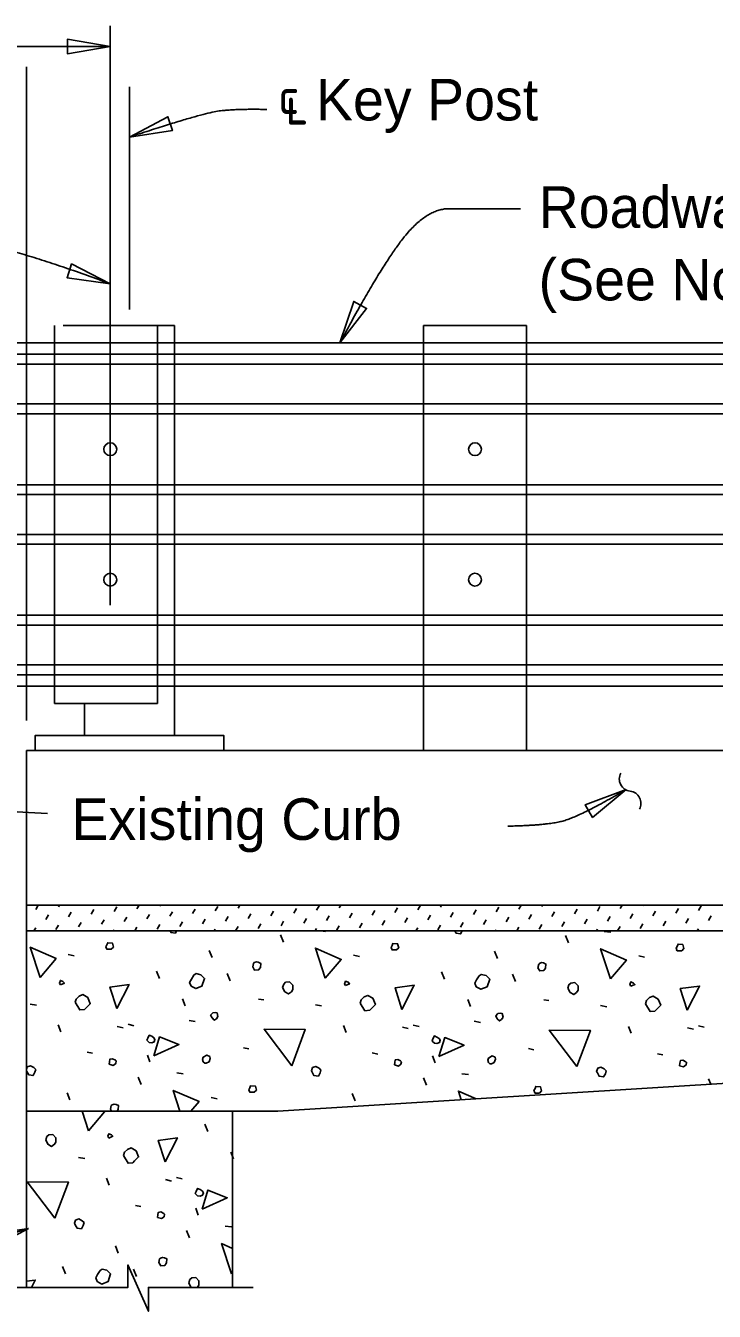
# Model space of a CAD drawing. Extents: x 21526.6 to 21598.7, y 56118.9 to 56155.9.
# Drawn here: x 21554.3 to 21557.64, y 56132.49 to 56138.73 of the extents above; entities that cross this region are included whole.
import ezdxf

# ---------------------------------------------------------------- set-up
doc = ezdxf.new("R2010")
doc.units = 0
for name, color, linetype in [('AdhocPoint_dp', 7, 'Continuous'), ('Border', 7, 'Continuous'), ('Patterning', 7, 'Continuous'), ('PlotBorder_dp', 7, 'Continuous'), ('SheetBorder_dp', 7, 'Continuous')]:
    doc.layers.add(name, color=color, linetype=linetype)

msp = doc.modelspace()

# ---------------------------------------------------------------- linework, layer by layer
at = {"layer": 'AdhocPoint_dp'}
for p, q in [((21554.3017, 56135.21), (21555.3017, 56135.21)), ((21554.3018, 56135.2101), (21554.3018, 56132.6054)), ((21554.3018, 56135.21), (21562.4118, 56135.21)), ((21565.8764, 56134.4601), (21554.3018, 56134.4601)), ((21554.3018, 56134.3351), (21565.8764, 56134.3351)), ((21559.5217, 56133.71), (21555.5217, 56133.46)), ((21555.5217, 56133.46), (21554.3017, 56133.46)), ((21555.3018, 56133.4601), (21555.3018, 56132.6054))]:
    msp.add_line(p, q, dxfattribs=at)
at = {"layer": 'Patterning'}
for p, q in [((21554.7081, 56135.9163), (21554.7081, 56138.7275)), ((21554.8018, 56138.4301), (21554.8018, 56137.3509)), ((21554.4372, 56137.2725), (21554.4372, 56135.4392)), ((21554.479, 56137.2725), (21555.0205, 56137.2725)), ((21554.9372, 56137.2725), (21554.9372, 56135.4392)), ((21556.2288, 56137.2725), (21556.2288, 56135.21)), ((21556.2288, 56137.2725), (21556.7288, 56137.2725)), ((21556.7288, 56137.2725), (21556.7288, 56135.21)), ((21554.3461, 56134.4388), (21554.3585, 56134.4601)), ((21554.4568, 56134.4517), (21554.4616, 56134.4601)), ((21554.8375, 56134.4418), (21554.8481, 56134.4601)), ((21554.9481, 56134.4548), (21554.9512, 56134.4601)), ((21555.3289, 56134.4448), (21555.3377, 56134.4601)), ((21555.4395, 56134.4578), (21555.4409, 56134.4601)), ((21555.7096, 56134.4349), (21555.7226, 56134.4573)), ((21555.8202, 56134.4478), (21555.8273, 56134.4601)), ((21556.201, 56134.4379), (21556.2138, 56134.4601)), ((21556.3116, 56134.4509), (21556.317, 56134.4601)), ((21556.6923, 56134.4409), (21556.7035, 56134.4601)), ((21556.803, 56134.4539), (21556.8066, 56134.4601)), ((21557.1837, 56134.4439), (21557.1931, 56134.4601)), ((21557.2943, 56134.4569), (21557.2962, 56134.4601)), ((21557.5644, 56134.434), (21557.5774, 56134.4564)), ((21554.395, 56134.3899), (21554.4079, 56134.4123)), ((21554.5056, 56134.4029), (21554.5186, 56134.4253)), ((21554.6162, 56134.4159), (21554.6292, 56134.4383)), ((21554.7269, 56134.4288), (21554.7398, 56134.4512)), ((21554.7757, 56134.38), (21554.7887, 56134.4024)), ((21554.8863, 56134.393), (21554.8993, 56134.4154)), ((21554.997, 56134.4059), (21555.0099, 56134.4283)), ((21555.1076, 56134.4189), (21555.1206, 56134.4413)), ((21555.2182, 56134.4319), (21555.2312, 56134.4542)), ((21555.2671, 56134.383), (21555.28, 56134.4054)), ((21555.3777, 56134.396), (21555.3907, 56134.4184)), ((21555.4883, 56134.4089), (21555.5013, 56134.4313)), ((21555.599, 56134.4219), (21555.6119, 56134.4443)), ((21555.6478, 56134.3731), (21555.6608, 56134.3955)), ((21555.7584, 56134.386), (21555.7714, 56134.4084)), ((21555.8691, 56134.399), (21555.882, 56134.4214)), ((21555.9797, 56134.412), (21555.9927, 56134.4344)), ((21556.0903, 56134.4249), (21556.1033, 56134.4473)), ((21556.1392, 56134.3761), (21556.1521, 56134.3985)), ((21556.2498, 56134.3891), (21556.2628, 56134.4115)), ((21556.3604, 56134.402), (21556.3734, 56134.4244)), ((21556.4711, 56134.415), (21556.484, 56134.4374)), ((21556.5817, 56134.428), (21556.5947, 56134.4503)), ((21556.6305, 56134.3791), (21556.6435, 56134.4015)), ((21556.7412, 56134.3921), (21556.7541, 56134.4145)), ((21556.8518, 56134.405), (21556.8648, 56134.4274)), ((21556.9624, 56134.418), (21556.9754, 56134.4404)), ((21557.0731, 56134.431), (21557.086, 56134.4534)), ((21557.1219, 56134.3821), (21557.1349, 56134.4045)), ((21557.2325, 56134.3951), (21557.2455, 56134.4175)), ((21557.3432, 56134.4081), (21557.3561, 56134.4305)), ((21557.4538, 56134.421), (21557.4668, 56134.4434)), ((21557.5026, 56134.3722), (21557.5156, 56134.3946)), ((21557.6133, 56134.3852), (21557.6262, 56134.4075)), ((21554.3372, 56134.3351), (21554.3461, 56134.3505)), ((21554.4438, 56134.3411), (21554.4568, 56134.3635)), ((21554.5544, 56134.3541), (21554.5674, 56134.3765)), ((21554.6651, 56134.367), (21554.678, 56134.3894)), ((21554.7237, 56134.3351), (21554.7269, 56134.3406)), ((21554.8268, 56134.3351), (21554.8375, 56134.3536)), ((21554.9352, 56134.3441), (21554.9481, 56134.3665)), ((21555.0458, 56134.3571), (21555.0588, 56134.3795)), ((21555.1564, 56134.3701), (21555.1694, 56134.3925)), ((21555.2133, 56134.3351), (21555.2182, 56134.3436)), ((21555.3164, 56134.3351), (21555.3289, 56134.3566)), ((21555.4265, 56134.3472), (21555.4395, 56134.3695)), ((21555.5372, 56134.3601), (21555.5501, 56134.3825)), ((21555.7029, 56134.3351), (21555.7096, 56134.3466)), ((21555.7313, 56134.3351), (21555.7532, 56134.3326)), ((21555.8073, 56134.3372), (21555.8202, 56134.3596)), ((21555.9179, 56134.3502), (21555.9309, 56134.3726)), ((21556.0285, 56134.3631), (21556.0415, 56134.3855)), ((21556.0894, 56134.3351), (21556.0903, 56134.3367)), ((21556.1925, 56134.3351), (21556.201, 56134.3497)), ((21556.2986, 56134.3402), (21556.3116, 56134.3626)), ((21556.4093, 56134.3532), (21556.4222, 56134.3756)), ((21556.5199, 56134.3662), (21556.5329, 56134.3885)), ((21556.579, 56134.3351), (21556.5817, 56134.3397)), ((21556.6821, 56134.3351), (21556.6923, 56134.3527)), ((21556.79, 56134.3432), (21556.803, 56134.3656)), ((21556.9006, 56134.3562), (21556.9136, 56134.3786)), ((21557.0113, 56134.3692), (21557.0242, 56134.3916)), ((21557.0686, 56134.3351), (21557.0731, 56134.3427)), ((21557.1061, 56134.3326), (21557.1379, 56134.3291)), ((21557.1718, 56134.3351), (21557.1837, 56134.3557)), ((21557.2814, 56134.3463), (21557.2943, 56134.3687)), ((21557.392, 56134.3592), (21557.405, 56134.3816)), ((21557.5582, 56134.3351), (21557.5644, 56134.3458)), ((21555.5488, 56134.2802), (21555.5346, 56134.3156)), ((21556.9334, 56134.2767), (21556.9193, 56134.312)), ((21554.5046, 56134.2213), (21554.5329, 56134.2142)), ((21555.2029, 56134.2054), (21555.1888, 56134.2407)), ((21555.8893, 56134.2177), (21555.9176, 56134.2107)), ((21556.5876, 56134.2018), (21556.5734, 56134.2372)), ((21557.274, 56134.2142), (21557.3023, 56134.2071)), ((21554.9466, 56134.1046), (21554.9324, 56134.1399)), ((21555.2907, 56134.0928), (21555.2765, 56134.1282)), ((21556.3313, 56134.1011), (21556.3171, 56134.1364)), ((21556.6753, 56134.0893), (21556.6612, 56134.1247)), ((21554.3196, 56133.9797), (21554.3497, 56133.9744)), ((21555.0721, 56133.972), (21555.0597, 56134.0056)), ((21555.4286, 56134.0045), (21555.4533, 56134.0009)), ((21555.7043, 56133.9762), (21555.7344, 56133.9709)), ((21556.4568, 56133.9685), (21556.4444, 56134.0021)), ((21556.8132, 56134.0009), (21556.838, 56133.9974)), ((21557.089, 56133.9726), (21557.1191, 56133.9673)), ((21555.0909, 56133.9002), (21555.121, 56133.8949)), ((21556.4756, 56133.8966), (21556.5056, 56133.8913)), ((21554.4681, 56133.8454), (21554.4558, 56133.8789)), ((21554.7421, 56133.8719), (21554.7704, 56133.8648)), ((21554.7945, 56133.8819), (21554.8228, 56133.8748)), ((21555.8528, 56133.8418), (21555.8404, 56133.8754)), ((21556.1268, 56133.8683), (21556.1551, 56133.8613)), ((21556.1792, 56133.8783), (21556.2075, 56133.8712)), ((21557.2375, 56133.8383), (21557.2251, 56133.8719)), ((21557.5115, 56133.8648), (21557.5398, 56133.8577)), ((21557.5639, 56133.8748), (21557.5922, 56133.8677)), ((21554.5954, 56133.7464), (21554.6219, 56133.7411)), ((21554.9006, 56133.6993), (21554.8882, 56133.7328)), ((21555.3543, 56133.7676), (21555.3808, 56133.7623)), ((21555.9801, 56133.7428), (21556.0066, 56133.7375)), ((21556.2853, 56133.6957), (21556.2729, 56133.7293)), ((21556.739, 56133.764), (21556.7655, 56133.7587)), ((21557.3648, 56133.7393), (21557.3913, 56133.734)), ((21555.0308, 56133.6456), (21555.0626, 56133.6421)), ((21554.8582, 56133.5897), (21554.844, 56133.625)), ((21556.2429, 56133.5861), (21556.2287, 56133.6215)), ((21556.4155, 56133.6421), (21556.4473, 56133.6385)), ((21557.624, 56133.5914), (21557.6134, 56133.6179)), ((21554.5123, 56133.5148), (21554.4982, 56133.5501)), ((21555.1987, 56133.5272), (21555.227, 56133.5201)), ((21555.897, 56133.5112), (21555.8829, 56133.5466)), ((21555.1813, 56133.3611), (21555.1671, 56133.3965)), ((21554.3017, 56133.2612), (21554.3033, 56133.261)), ((21554.5543, 56133.2362), (21554.5844, 56133.2309)), ((21555.3068, 56133.2285), (21555.2944, 56133.2621)), ((21554.7028, 56133.1019), (21554.6905, 56133.1355)), ((21554.9768, 56133.1284), (21555.0051, 56133.1213)), ((21555.0292, 56133.1384), (21555.0575, 56133.1313)), ((21554.8301, 56133.0029), (21554.8566, 56132.9976)), ((21555.1353, 56132.9558), (21555.1229, 56132.9894)), ((21555.2655, 56132.9021), (21555.2973, 56132.8986)), ((21555.0929, 56132.8462), (21555.0787, 56132.8815)), ((21554.747, 56132.7713), (21554.7329, 56132.8067)), ((21554.4907, 56132.6706), (21554.4766, 56132.7059)), ((21554.8348, 56132.6588), (21554.8206, 56132.6942))]:
    msp.add_line(p, q, dxfattribs=at)
for points in [[(21554.9988, 56134.3351), (21555.0031, 56134.3273), (21555.0244, 56134.3238), (21555.0306, 56134.3351)], [(21556.3816, 56134.3351), (21556.3878, 56134.3238), (21556.409, 56134.3203), (21556.4173, 56134.3351)], [(21554.692, 56134.246), (21554.7132, 56134.246), (21554.7238, 56134.2566), (21554.7185, 56134.2761), (21554.6956, 56134.2778), (21554.692, 56134.2672), (21554.6867, 56134.2584), (21554.692, 56134.246), (21554.6885, 56134.2495)], [(21556.0767, 56134.2425), (21556.0979, 56134.2425), (21556.1085, 56134.2531), (21556.1032, 56134.2725), (21556.0802, 56134.2743), (21556.0767, 56134.2637), (21556.0714, 56134.2549), (21556.0767, 56134.2425), (21556.0732, 56134.246)], [(21557.4614, 56134.2389), (21557.4826, 56134.2389), (21557.4932, 56134.2495), (21557.4879, 56134.269), (21557.4649, 56134.2708), (21557.4614, 56134.2602), (21557.4561, 56134.2513), (21557.4614, 56134.2389), (21557.4578, 56134.2425)], [(21554.3674, 56134.1088), (21554.3196, 56134.2555), (21554.4452, 56134.2007), (21554.3674, 56134.1088)], [(21555.7521, 56134.1052), (21555.7043, 56134.2519), (21555.8298, 56134.1971), (21555.7521, 56134.1052)], [(21557.1367, 56134.1017), (21557.089, 56134.2484), (21557.2145, 56134.1936), (21557.1367, 56134.1017)], [(21555.4003, 56134.16), (21555.4091, 56134.1441), (21555.4286, 56134.1459), (21555.4374, 56134.1582), (21555.4392, 56134.1777), (21555.4268, 56134.183), (21555.4179, 56134.1848), (21555.4073, 56134.1812), (21555.4038, 56134.1777), (21555.4003, 56134.16)], [(21556.7849, 56134.1565), (21556.7938, 56134.1406), (21556.8132, 56134.1423), (21556.8221, 56134.1547), (21556.8238, 56134.1742), (21556.8115, 56134.1795), (21556.8026, 56134.1812), (21556.792, 56134.1777), (21556.7885, 56134.1742), (21556.7849, 56134.1565)], [(21554.4664, 56134.0734), (21554.4858, 56134.0822), (21554.4787, 56134.0893), (21554.4664, 56134.0946), (21554.4611, 56134.0822), (21554.4664, 56134.0734)], [(21555.1004, 56134.0675), (21555.1234, 56134.0551), (21555.1534, 56134.0675), (21555.1658, 56134.1046), (21555.1481, 56134.1223), (21555.1251, 56134.1276), (21555.1145, 56134.1205), (21555.1021, 56134.1011), (21555.0933, 56134.0851), (21555.1004, 56134.0675)], [(21555.5452, 56134.061), (21555.5558, 56134.0398), (21555.5735, 56134.0292), (21555.5876, 56134.0398), (21555.5947, 56134.0504), (21555.5947, 56134.0716), (21555.5788, 56134.0875), (21555.5594, 56134.0858), (21555.5505, 56134.0769), (21555.5452, 56134.061)], [(21555.851, 56134.0699), (21555.8705, 56134.0787), (21555.8634, 56134.0858), (21555.851, 56134.0911), (21555.8457, 56134.0787), (21555.851, 56134.0699)], [(21556.485, 56134.0639), (21556.508, 56134.0516), (21556.5381, 56134.0639), (21556.5505, 56134.1011), (21556.5328, 56134.1187), (21556.5098, 56134.124), (21556.4992, 56134.117), (21556.4868, 56134.0975), (21556.478, 56134.0816), (21556.485, 56134.0639)], [(21556.9299, 56134.0575), (21556.9405, 56134.0363), (21556.9582, 56134.0257), (21556.9723, 56134.0363), (21556.9794, 56134.0469), (21556.9794, 56134.0681), (21556.9635, 56134.084), (21556.944, 56134.0822), (21556.9352, 56134.0734), (21556.9299, 56134.0575)], [(21557.2357, 56134.0663), (21557.2552, 56134.0752), (21557.2481, 56134.0822), (21557.2357, 56134.0875), (21557.2304, 56134.0752), (21557.2357, 56134.0663)], [(21554.5371, 56133.9885), (21554.5601, 56133.9514), (21554.583, 56133.9532), (21554.5919, 56133.962), (21554.6113, 56133.9815), (21554.599, 56134.0115), (21554.5742, 56134.0257), (21554.5565, 56134.0186), (21554.5424, 56134.0045), (21554.5371, 56133.9885)], [(21554.7397, 56133.9579), (21554.7062, 56134.0622), (21554.7999, 56134.0745), (21554.7397, 56133.9579)], [(21555.9218, 56133.985), (21555.9447, 56133.9479), (21555.9677, 56133.9497), (21555.9766, 56133.9585), (21555.996, 56133.9779), (21555.9836, 56134.008), (21555.9589, 56134.0221), (21555.9412, 56134.0151), (21555.9271, 56134.0009), (21555.9218, 56133.985)], [(21556.1244, 56133.9543), (21556.0908, 56134.0586), (21556.1845, 56134.071), (21556.1244, 56133.9543)], [(21557.5091, 56133.9508), (21557.4755, 56134.0551), (21557.5692, 56134.0675), (21557.5091, 56133.9508)], [(21557.3064, 56133.9815), (21557.3294, 56133.9444), (21557.3524, 56133.9461), (21557.3612, 56133.955), (21557.3807, 56133.9744), (21557.3683, 56134.0045), (21557.3436, 56134.0186), (21557.3259, 56134.0115), (21557.3117, 56133.9974), (21557.3064, 56133.9815)], [(21555.2023, 56133.9125), (21555.2129, 56133.9019), (21555.2235, 56133.909), (21555.2306, 56133.9196), (21555.227, 56133.9373), (21555.2182, 56133.939), (21555.2058, 56133.9373), (21555.1952, 56133.9267), (21555.2023, 56133.9125)], [(21556.587, 56133.909), (21556.5976, 56133.8984), (21556.6082, 56133.9055), (21556.6152, 56133.9161), (21556.6117, 56133.9337), (21556.6029, 56133.9355), (21556.5905, 56133.9337), (21556.5799, 56133.9231), (21556.587, 56133.909)], [(21555.5894, 56133.681), (21555.4551, 56133.8577), (21555.6548, 56133.856), (21555.5894, 56133.681)], [(21556.9741, 56133.6774), (21556.8397, 56133.8542), (21557.0395, 56133.8524), (21556.9741, 56133.6774)], [(21554.8971, 56133.7935), (21554.9095, 56133.7917), (21554.9218, 56133.797), (21554.9254, 56133.8076), (21554.9201, 56133.8164), (21554.9095, 56133.8235), (21554.8971, 56133.8288), (21554.89, 56133.8147), (21554.8865, 56133.8041), (21554.8971, 56133.7935)], [(21554.9194, 56133.7287), (21554.9477, 56133.8206), (21555.0414, 56133.7835), (21554.9194, 56133.7287)], [(21556.2818, 56133.7899), (21556.2941, 56133.7882), (21556.3065, 56133.7935), (21556.31, 56133.8041), (21556.3047, 56133.8129), (21556.2941, 56133.82), (21556.2818, 56133.8253), (21556.2747, 56133.8111), (21556.2711, 56133.8005), (21556.2818, 56133.7899)], [(21556.3041, 56133.7251), (21556.3324, 56133.8171), (21556.4261, 56133.7799), (21556.3041, 56133.7251)], [(21554.7033, 56133.688), (21554.7227, 56133.6827), (21554.7351, 56133.6916), (21554.7368, 56133.7039), (21554.7333, 56133.7075), (21554.7192, 56133.7145), (21554.7068, 56133.7128), (21554.705, 56133.7004), (21554.7033, 56133.688)], [(21555.1669, 56133.6933), (21555.174, 56133.6933), (21555.1881, 56133.7004), (21555.1934, 56133.7163), (21555.1917, 56133.7251), (21555.1775, 56133.7322), (21555.1598, 56133.7216), (21555.1563, 56133.711), (21555.1598, 56133.7004), (21555.1669, 56133.6933)], [(21556.0879, 56133.6845), (21556.1074, 56133.6792), (21556.1197, 56133.688), (21556.1215, 56133.7004), (21556.118, 56133.7039), (21556.1038, 56133.711), (21556.0915, 56133.7092), (21556.0897, 56133.6969), (21556.0879, 56133.6845)], [(21556.5516, 56133.6898), (21556.5587, 56133.6898), (21556.5728, 56133.6969), (21556.5781, 56133.7128), (21556.5763, 56133.7216), (21556.5622, 56133.7287), (21556.5445, 56133.7181), (21556.541, 56133.7075), (21556.5445, 56133.6969), (21556.5516, 56133.6898)], [(21557.4726, 56133.681), (21557.492, 56133.6756), (21557.5044, 56133.6845), (21557.5062, 56133.6969), (21557.5027, 56133.7004), (21557.4885, 56133.7075), (21557.4761, 56133.7057), (21557.4744, 56133.6933), (21557.4726, 56133.681)], [(21554.3037, 56133.6527), (21554.3126, 56133.6368), (21554.3338, 56133.6332), (21554.3426, 56133.6491), (21554.3462, 56133.6633), (21554.3373, 56133.6721), (21554.3214, 56133.681), (21554.3055, 56133.6756), (21554.3017, 56133.6643)], [(21554.3017, 56133.6567), (21554.3037, 56133.6527)], [(21555.6884, 56133.6491), (21555.6973, 56133.6332), (21555.7185, 56133.6297), (21555.7273, 56133.6456), (21555.7308, 56133.6597), (21555.722, 56133.6686), (21555.7061, 56133.6774), (21555.6902, 56133.6721), (21555.6849, 56133.6562), (21555.6884, 56133.6491)], [(21557.0731, 56133.6456), (21557.0819, 56133.6297), (21557.1031, 56133.6262), (21557.112, 56133.6421), (21557.1155, 56133.6562), (21557.1067, 56133.665), (21557.0908, 56133.6739), (21557.0749, 56133.6686), (21557.0696, 56133.6527), (21557.0731, 56133.6456)], [(21555.3861, 56133.5519), (21555.4073, 56133.5519), (21555.4179, 56133.5625), (21555.4126, 56133.582), (21555.3897, 56133.5837), (21555.3861, 56133.5731), (21555.3808, 56133.5643), (21555.3861, 56133.5519), (21555.3826, 56133.5554)], [(21555.0467, 56133.46), (21555.0138, 56133.5614), (21555.1393, 56133.5066), (21555.0999, 56133.46)], [(21556.4121, 56133.5157), (21556.3984, 56133.5578), (21556.4846, 56133.5202)], [(21556.7708, 56133.5484), (21556.792, 56133.5484), (21556.8026, 56133.559), (21556.7973, 56133.5784), (21556.7743, 56133.5802), (21556.7708, 56133.5696), (21556.7655, 56133.5607), (21556.7708, 56133.5484), (21556.7673, 56133.5519)], [(21554.6021, 56133.3653), (21554.5713, 56133.46)], [(21554.6734, 56133.46), (21554.6798, 56133.4572), (21554.6021, 56133.3653)], [(21554.7413, 56133.46), (21554.7468, 56133.4677), (21554.7486, 56133.4871), (21554.7362, 56133.4924), (21554.7274, 56133.4942), (21554.7168, 56133.4907), (21554.7132, 56133.4871), (21554.7097, 56133.4694)], [(21554.7097, 56133.4694), (21554.7149, 56133.46)], [(21554.3952, 56133.3211), (21554.4058, 56133.2999), (21554.4235, 56133.2893), (21554.4377, 56133.2999), (21554.4447, 56133.3105), (21554.4447, 56133.3317), (21554.4288, 56133.3476), (21554.4094, 56133.3458), (21554.4005, 56133.337), (21554.3952, 56133.3211)], [(21554.7011, 56133.3299), (21554.7205, 56133.3388), (21554.7134, 56133.3458), (21554.7011, 56133.3511), (21554.6958, 56133.3388), (21554.7011, 56133.3299)], [(21554.7718, 56133.2451), (21554.7948, 56133.208), (21554.8177, 56133.2097), (21554.8266, 56133.2186), (21554.846, 56133.238), (21554.8336, 56133.2681), (21554.8089, 56133.2822), (21554.7912, 56133.2751), (21554.7771, 56133.261), (21554.7718, 56133.2451)], [(21554.9744, 56133.2144), (21554.9409, 56133.3187), (21555.0345, 56133.3311), (21554.9744, 56133.2144)], [(21554.4394, 56132.941), (21554.3051, 56133.1178), (21554.5048, 56133.116), (21554.4394, 56132.941)], [(21555.1318, 56133.05), (21555.1441, 56133.0482), (21555.1565, 56133.0535), (21555.1601, 56133.0641), (21555.1548, 56133.073), (21555.1441, 56133.0801), (21555.1318, 56133.0854), (21555.1247, 56133.0712), (21555.1212, 56133.0606), (21555.1318, 56133.05)], [(21555.1541, 56132.9852), (21555.1824, 56133.0771), (21555.2761, 56133.04), (21555.1541, 56132.9852)], [(21554.9379, 56132.9446), (21554.9574, 56132.9393), (21554.9698, 56132.9481), (21554.9715, 56132.9605), (21554.968, 56132.964), (21554.9539, 56132.9711), (21554.9415, 56132.9693), (21554.9397, 56132.9569), (21554.9379, 56132.9446)], [(21554.5384, 56132.9092), (21554.5473, 56132.8933), (21554.5685, 56132.8898), (21554.5773, 56132.9057), (21554.5809, 56132.9198), (21554.572, 56132.9287), (21554.5561, 56132.9375), (21554.5402, 56132.9322), (21554.5349, 56132.9163), (21554.5384, 56132.9092)], [(21555.2962, 56132.6712), (21555.2484, 56132.8179), (21555.3018, 56132.7946)], [(21554.9444, 56132.726), (21554.9532, 56132.7101), (21554.9727, 56132.7118), (21554.9815, 56132.7242), (21554.9833, 56132.7437), (21554.9709, 56132.749), (21554.9621, 56132.7507), (21554.9515, 56132.7472), (21554.9479, 56132.7437), (21554.9444, 56132.726)], [(21554.6445, 56132.6334), (21554.6675, 56132.6211), (21554.6975, 56132.6334), (21554.7099, 56132.6706), (21554.6922, 56132.6882), (21554.6692, 56132.6935), (21554.6586, 56132.6865), (21554.6463, 56132.667), (21554.6374, 56132.6511), (21554.6445, 56132.6334)], [(21555.1313, 56132.6054), (21555.1318, 56132.6058), (21555.1388, 56132.6164), (21555.1388, 56132.6376), (21555.1229, 56132.6535), (21555.1035, 56132.6517), (21555.0946, 56132.6429), (21555.0893, 56132.627)], [(21554.3018, 56132.6349), (21554.344, 56132.6405), (21554.3259, 56132.6054)], [(21555.0893, 56132.627), (21555.1, 56132.6058), (21555.1005, 56132.6054)]]:
    msp.add_lwpolyline(points, dxfattribs=at)
for centre in [(21554.7081, 56136.6724), (21554.7081, 56136.0393)]:
    msp.add_circle(centre, 0.0312, dxfattribs=at)
at = {"layer": 'PlotBorder_dp'}
for p, q in [((21554.7081, 56138.6268), (21552.3714, 56138.6268)), ((21554.3017, 56135.3555), (21554.3017, 56138.5276))]:
    msp.add_line(p, q, dxfattribs=at)
for points in [[(21554.7081, 56138.6268), (21554.4998, 56138.6621), (21554.4998, 56138.5915)], [(21554.8014, 56138.187), (21555.0101, 56138.2189), (21554.988, 56138.2859)], [(21554.7081, 56137.4747), (21554.5204, 56137.5715), (21554.4989, 56137.5043)], [(21555.8233, 56137.1892), (21555.9529, 56137.356), (21555.8907, 56137.3893)], [(21557.2128, 56135.0207), (21557.0501, 56134.8859), (21557.0148, 56134.947)], [(21554.3117, 56132.8915), (21554.1029, 56132.8596), (21554.1251, 56132.7926)]]:
    msp.add_lwpolyline(points, close=True, dxfattribs=at)
msp.add_lwpolyline([(21555.4018, 56132.6055), (21554.8932, 56132.6055), (21554.8932, 56132.4893), (21554.7938, 56132.7143), (21554.7938, 56132.6055), (21554.2018, 56132.6055)], dxfattribs=at)
for centre, start, end in [((21557.2394, 56135.0721), 151.52667, 263.25389), ((21557.2254, 56134.9537), 331.52667, 83.25389)]:
    msp.add_arc(centre, 0.0596, start, end, dxfattribs=at)
for points, degree in [([(21555.4691, 56138.3212), (21555.335, 56138.324), (21555.1638, 56138.3069), (21554.8014, 56138.187)], 2), ([(21556.6997, 56137.8396), (21556.4594, 56137.8396), (21556.2473, 56137.8396), (21556.0283, 56137.571), (21555.8233, 56137.1892)], 2), ([(21552.7287, 56137.7519), (21553.3051, 56137.7529), (21554.0547, 56137.7205), (21554.7081, 56137.4746)], 2), ([(21556.6378, 56134.8434), (21556.8234, 56134.8469), (21556.9842, 56134.8885), (21557.2128, 56135.0207)], 2), ([(21554.4035, 56134.9046), (21553.8821, 56134.9384), (21553.7786, 56134.9162), (21553.6846, 56134.8796), (21553.5135, 56134.6171)], 3), ([(21554.3117, 56132.8915), (21553.648, 56132.6719), (21552.9843, 56132.6719)], 2)]:
    msp.add_open_spline(points, degree=degree, dxfattribs=at)
at = {"layer": 'SheetBorder_dp'}
for p, q in [((21555.0205, 56137.2725), (21555.0205, 56135.283)), ((21564.1633, 56137.1891), (21552.8484, 56137.1891)), ((21552.8484, 56137.1336), (21564.1633, 56137.1336)), ((21552.8484, 56137.0853), (21564.1633, 56137.0853)), ((21552.8484, 56136.8925), (21564.1633, 56136.8925)), ((21552.8484, 56136.8443), (21564.1633, 56136.8443)), ((21552.8484, 56136.5003), (21564.1633, 56136.5003)), ((21552.8484, 56136.4521), (21564.1633, 56136.4521)), ((21552.8484, 56136.2593), (21564.1633, 56136.2593)), ((21552.8484, 56136.2112), (21564.1633, 56136.2112)), ((21552.8484, 56135.8672), (21564.1633, 56135.8672)), ((21552.8484, 56135.819), (21564.1633, 56135.819)), ((21552.8484, 56135.6262), (21564.1633, 56135.6262)), ((21552.8484, 56135.5779), (21564.1633, 56135.5779)), ((21564.1633, 56135.5224), (21552.8484, 56135.5224)), ((21554.9372, 56135.4392), (21554.4372, 56135.4392)), ((21554.583, 56135.4392), (21554.583, 56135.283))]:
    msp.add_line(p, q, dxfattribs=at)
msp.add_lwpolyline([(21554.3434, 56135.21), (21554.3434, 56135.283), (21555.2601, 56135.283), (21555.2601, 56135.21)], close=True, dxfattribs=at)
for centre in [(21556.4788, 56136.6724), (21556.4788, 56136.0393)]:
    msp.add_circle(centre, 0.0312, dxfattribs=at)

# ---------------------------------------------------------------- texts
at = {"layer": 'Border'}
for s, p in [('℄ Key Post', (21555.5227, 56138.2678)), ('Existing Curb', (21554.5197, 56134.7766))]:
    msp.add_text(s, height=0.2016, dxfattribs=at).set_placement(p)
at = {"layer": 'PlotBorder_dp'}
for s, p in [('Roadway Guardrail Transition', (21556.788, 56137.7466)), ('(See Note 1, Sheet 1)', (21556.788, 56137.3946))]:
    msp.add_text(s, height=0.2016, dxfattribs=at).set_placement(p)

doc.saveas('drawing.dxf')
